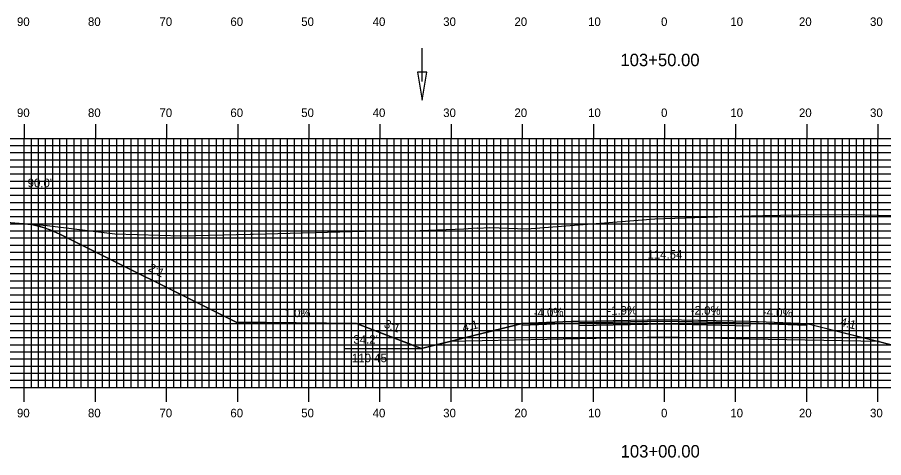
# Model space of a CAD drawing. Extents: x 1767300 to 1767643, y 442591 to 442811.
# Drawn here: x 1767375 to 1767496.7, y 442653.8 to 442715.7 of the extents above; entities that cross this region are included whole.
import ezdxf

# ---------------------------------------------------------------- set-up
doc = ezdxf.new("R2010")
doc.units = 0
for name, color, linetype in [('ANNOTATION', 7, 'Continuous'), ('D_Drainage_Ditch_Line', 7, 'Continuous'), ('D_Roadway_Centerline', 7, 'Continuous'), ('D_Roadway_Centerline_Text', 7, 'Continuous'), ('D_Roadway_Edge_Shoulder', 7, 'Continuous'), ('D_Roadway_Edge_TW', 7, 'Continuous'), ('D_Roadway_Pavement', 7, 'Continuous'), ('D_Roadway_SlopeLines', 7, 'Continuous'), ('D_Roadway_SubGrade', 7, 'Continuous'), ('D_Text_Standard', 7, 'Continuous'), ('H_V ANNOTATION', 7, 'Continuous'), ('MAJOR', 7, 'Continuous'), ('MINOR', 7, 'Continuous'), ('PDRAIN', 7, 'Continuous'), ('S_Roadway_Centerline', 7, 'Continuous')]:
    doc.layers.add(name, color=color, linetype=linetype)

msp = doc.modelspace()

# ---------------------------------------------------------------- linework, layer by layer
at = {"layer": 'D_Drainage_Ditch_Line'}
msp.add_line((1767431.87, 442706.66), (1767431.87, 442711.36), dxfattribs=at)
msp.add_lwpolyline([(1767432.53, 442707.97), (1767431.22, 442707.97), (1767431.87, 442704.03)], close=True, dxfattribs=at)
at = {"layer": 'D_Roadway_Centerline'}
msp.add_lwpolyline([(1767375.94, 442686.68), (1767376.9, 442686.55), (1767377.19, 442686.51), (1767377.74, 442686.38), (1767378.44, 442686.21), (1767378.79, 442686.09), (1767379.69, 442685.78), (1767380.94, 442685.22), (1767405.72, 442672.83), (1767405.72, 442672.83), (1767410.78, 442672.78), (1767422.65, 442672.66), (1767422.65, 442672.66), (1767430.73, 442669.52), (1767431.76, 442669.12), (1767432.36, 442669.27), (1767435.76, 442670.12), (1767445.94, 442672.66), (1767453.94, 442672.98), (1767465.94, 442673.21), (1767477.93, 442672.97), (1767477.94, 442672.97), (1767482.58, 442672.78), (1767485.94, 442672.65), (1767491.01, 442671.38), (1767496.11, 442670.1), (1767496.11, 442670.1), (1767500.11, 442669.1)], dxfattribs=at)
at = {"layer": 'D_Roadway_Edge_Shoulder'}
for points in [[(1767453.94, 442672.98), (1767445.94, 442672.66), (1767445.94, 442672.41), (1767453.94, 442672.73)], [(1767477.94, 442672.97), (1767485.94, 442672.65), (1767485.94, 442672.4), (1767477.94, 442672.72)]]:
    msp.add_lwpolyline(points, close=True, dxfattribs=at)
at = {"layer": 'D_Roadway_Edge_TW'}
msp.add_lwpolyline([(1767453.94, 442672.73), (1767453.94, 442672.98), (1767465.94, 442673.21), (1767477.94, 442672.97), (1767477.94, 442672.72), (1767465.94, 442672.96)], close=True, dxfattribs=at)
at = {"layer": 'D_Roadway_Pavement'}
msp.add_lwpolyline([(1767453.94, 442672.32), (1767453.94, 442672.73), (1767465.94, 442672.96), (1767477.94, 442672.72), (1767477.94, 442672.3), (1767465.94, 442672.54)], close=True, dxfattribs=at)
at = {"layer": 'D_Roadway_SlopeLines'}
for points in [[(1767422.65, 442672.66), (1767405.72, 442672.83), (1767380.94, 442685.22), (1767379.69, 442685.78), (1767378.44, 442686.21), (1767377.19, 442686.51), (1767375.94, 442686.68)], [(1767431.76, 442669.12), (1767422.65, 442672.66)], [(1767445.94, 442672.66), (1767431.76, 442669.12)], [(1767485.94, 442672.65), (1767500.11, 442669.1)]]:
    msp.add_lwpolyline(points, dxfattribs=at)
at = {"layer": 'D_Roadway_SubGrade'}
msp.add_lwpolyline([(1767453.94, 442670.48), (1767435.76, 442670.12), (1767445.94, 442672.66), (1767445.94, 442672.41), (1767453.94, 442672.73), (1767465.94, 442672.96), (1767477.94, 442672.72), (1767485.94, 442672.4), (1767485.94, 442672.65), (1767496.11, 442670.1), (1767477.94, 442670.47), (1767465.94, 442670.71)], close=True, dxfattribs=at)
at = {"layer": 'MAJOR'}
for p, q in [((1767375.94, 442700.67), (1767375.94, 442698.67)), ((1767385.94, 442700.67), (1767385.94, 442698.67)), ((1767395.94, 442700.67), (1767395.94, 442698.67)), ((1767405.94, 442700.67), (1767405.94, 442698.67)), ((1767415.94, 442700.67), (1767415.94, 442698.67)), ((1767425.94, 442700.67), (1767425.94, 442698.67)), ((1767435.94, 442700.67), (1767435.94, 442698.67)), ((1767445.94, 442700.67), (1767445.94, 442698.67)), ((1767455.94, 442700.67), (1767455.94, 442698.67)), ((1767465.94, 442700.67), (1767465.94, 442698.67)), ((1767475.94, 442700.67), (1767475.94, 442698.67)), ((1767485.94, 442700.67), (1767485.94, 442698.67)), ((1767495.94, 442700.67), (1767495.94, 442698.67)), ((1767325.94, 442698.67), (1767605.94, 442698.67)), ((1767325.94, 442698.67), (1767605.94, 442698.67)), ((1767375.94, 442663.67), (1767375.94, 442698.67)), ((1767385.94, 442663.67), (1767385.94, 442698.67)), ((1767395.94, 442663.67), (1767395.94, 442698.67)), ((1767405.94, 442663.67), (1767405.94, 442698.67)), ((1767415.94, 442663.67), (1767415.94, 442698.67)), ((1767425.94, 442663.67), (1767425.94, 442698.67)), ((1767435.94, 442663.67), (1767435.94, 442698.67)), ((1767445.94, 442663.67), (1767445.94, 442698.67)), ((1767455.94, 442663.67), (1767455.94, 442698.67)), ((1767465.94, 442663.67), (1767465.94, 442698.67)), ((1767475.94, 442663.67), (1767475.94, 442698.67)), ((1767485.94, 442663.67), (1767485.94, 442698.67)), ((1767495.94, 442663.67), (1767495.94, 442698.67)), ((1767325.94, 442693.67), (1767605.94, 442693.67)), ((1767325.94, 442688.67), (1767605.94, 442688.67)), ((1767325.94, 442683.67), (1767605.94, 442683.67)), ((1767325.94, 442678.67), (1767605.94, 442678.67)), ((1767325.94, 442673.67), (1767605.94, 442673.67)), ((1767325.94, 442668.67), (1767605.94, 442668.67)), ((1767325.94, 442663.67), (1767605.94, 442663.67)), ((1767325.94, 442663.67), (1767605.94, 442663.67)), ((1767375.94, 442661.66), (1767375.94, 442663.67)), ((1767385.94, 442661.66), (1767385.94, 442663.67)), ((1767395.94, 442661.66), (1767395.94, 442663.67)), ((1767405.94, 442661.66), (1767405.94, 442663.67)), ((1767415.94, 442661.66), (1767415.94, 442663.67)), ((1767425.94, 442661.66), (1767425.94, 442663.67)), ((1767435.94, 442661.66), (1767435.94, 442663.67)), ((1767445.94, 442661.66), (1767445.94, 442663.67)), ((1767455.94, 442661.66), (1767455.94, 442663.67)), ((1767465.94, 442661.66), (1767465.94, 442663.67)), ((1767475.94, 442661.66), (1767475.94, 442663.67)), ((1767485.94, 442661.66), (1767485.94, 442663.67)), ((1767495.94, 442661.66), (1767495.94, 442663.67))]:
    msp.add_line(p, q, dxfattribs=at)
at = {"layer": 'MINOR'}
for p, q in [((1767376.94, 442663.67), (1767376.94, 442698.67)), ((1767377.94, 442663.67), (1767377.94, 442698.67)), ((1767378.94, 442663.67), (1767378.94, 442698.67)), ((1767379.94, 442663.67), (1767379.94, 442698.67)), ((1767380.94, 442663.67), (1767380.94, 442698.67)), ((1767381.94, 442663.67), (1767381.94, 442698.67)), ((1767382.94, 442663.67), (1767382.94, 442698.67)), ((1767383.94, 442663.67), (1767383.94, 442698.67)), ((1767384.94, 442663.67), (1767384.94, 442698.67)), ((1767386.94, 442663.67), (1767386.94, 442698.67)), ((1767387.94, 442663.67), (1767387.94, 442698.67)), ((1767388.94, 442663.67), (1767388.94, 442698.67)), ((1767389.94, 442663.67), (1767389.94, 442698.67)), ((1767390.94, 442663.67), (1767390.94, 442698.67)), ((1767391.94, 442663.67), (1767391.94, 442698.67)), ((1767392.94, 442663.67), (1767392.94, 442698.67)), ((1767393.94, 442663.67), (1767393.94, 442698.67)), ((1767394.94, 442663.67), (1767394.94, 442698.67)), ((1767396.94, 442663.67), (1767396.94, 442698.67)), ((1767397.94, 442663.67), (1767397.94, 442698.67)), ((1767398.94, 442663.67), (1767398.94, 442698.67)), ((1767399.94, 442663.67), (1767399.94, 442698.67)), ((1767400.94, 442663.67), (1767400.94, 442698.67)), ((1767401.94, 442663.67), (1767401.94, 442698.67)), ((1767402.94, 442663.67), (1767402.94, 442698.67)), ((1767403.94, 442663.67), (1767403.94, 442698.67)), ((1767404.94, 442663.67), (1767404.94, 442698.67)), ((1767406.94, 442663.67), (1767406.94, 442698.67)), ((1767407.94, 442663.67), (1767407.94, 442698.67)), ((1767408.94, 442663.67), (1767408.94, 442698.67)), ((1767409.94, 442663.67), (1767409.94, 442698.67)), ((1767410.94, 442663.67), (1767410.94, 442698.67)), ((1767411.94, 442663.67), (1767411.94, 442698.67)), ((1767412.94, 442663.67), (1767412.94, 442698.67)), ((1767413.94, 442663.67), (1767413.94, 442698.67)), ((1767414.94, 442663.67), (1767414.94, 442698.67)), ((1767416.94, 442663.67), (1767416.94, 442698.67)), ((1767417.94, 442663.67), (1767417.94, 442698.67)), ((1767418.94, 442663.67), (1767418.94, 442698.67)), ((1767419.94, 442663.67), (1767419.94, 442698.67)), ((1767420.94, 442663.67), (1767420.94, 442698.67)), ((1767421.94, 442663.67), (1767421.94, 442698.67)), ((1767422.94, 442663.67), (1767422.94, 442698.67)), ((1767423.94, 442663.67), (1767423.94, 442698.67)), ((1767424.94, 442663.67), (1767424.94, 442698.67)), ((1767426.94, 442663.67), (1767426.94, 442698.67)), ((1767427.94, 442663.67), (1767427.94, 442698.67)), ((1767428.94, 442663.67), (1767428.94, 442698.67)), ((1767429.94, 442663.67), (1767429.94, 442698.67)), ((1767430.94, 442663.67), (1767430.94, 442698.67)), ((1767431.94, 442663.67), (1767431.94, 442698.67)), ((1767432.94, 442663.67), (1767432.94, 442698.67)), ((1767433.94, 442663.67), (1767433.94, 442698.67)), ((1767434.94, 442663.67), (1767434.94, 442698.67)), ((1767436.94, 442663.67), (1767436.94, 442698.67)), ((1767437.94, 442663.67), (1767437.94, 442698.67)), ((1767438.94, 442663.67), (1767438.94, 442698.67)), ((1767439.94, 442663.67), (1767439.94, 442698.67)), ((1767440.94, 442663.67), (1767440.94, 442698.67)), ((1767441.94, 442663.67), (1767441.94, 442698.67)), ((1767442.94, 442663.67), (1767442.94, 442698.67)), ((1767443.94, 442663.67), (1767443.94, 442698.67)), ((1767444.94, 442663.67), (1767444.94, 442698.67)), ((1767446.94, 442663.67), (1767446.94, 442698.67)), ((1767447.94, 442663.67), (1767447.94, 442698.67)), ((1767448.94, 442663.67), (1767448.94, 442698.67)), ((1767449.94, 442663.67), (1767449.94, 442698.67)), ((1767450.94, 442663.67), (1767450.94, 442698.67)), ((1767451.94, 442663.67), (1767451.94, 442698.67)), ((1767452.94, 442663.67), (1767452.94, 442698.67)), ((1767453.94, 442663.67), (1767453.94, 442698.67)), ((1767454.94, 442663.67), (1767454.94, 442698.67)), ((1767456.94, 442663.67), (1767456.94, 442698.67)), ((1767457.94, 442663.67), (1767457.94, 442698.67)), ((1767458.94, 442663.67), (1767458.94, 442698.67)), ((1767459.94, 442663.67), (1767459.94, 442698.67)), ((1767460.94, 442663.67), (1767460.94, 442698.67)), ((1767461.94, 442663.67), (1767461.94, 442698.67)), ((1767462.94, 442663.67), (1767462.94, 442698.67)), ((1767463.94, 442663.67), (1767463.94, 442698.67)), ((1767464.94, 442663.67), (1767464.94, 442698.67)), ((1767466.94, 442663.67), (1767466.94, 442698.67)), ((1767467.94, 442663.67), (1767467.94, 442698.67)), ((1767468.94, 442663.67), (1767468.94, 442698.67)), ((1767469.94, 442663.67), (1767469.94, 442698.67)), ((1767470.94, 442663.67), (1767470.94, 442698.67)), ((1767471.94, 442663.67), (1767471.94, 442698.67)), ((1767472.94, 442663.67), (1767472.94, 442698.67)), ((1767473.94, 442663.67), (1767473.94, 442698.67)), ((1767474.94, 442663.67), (1767474.94, 442698.67)), ((1767476.94, 442663.67), (1767476.94, 442698.67)), ((1767477.94, 442663.67), (1767477.94, 442698.67)), ((1767478.94, 442663.67), (1767478.94, 442698.67)), ((1767479.94, 442663.67), (1767479.94, 442698.67)), ((1767480.94, 442663.67), (1767480.94, 442698.67)), ((1767481.94, 442663.67), (1767481.94, 442698.67)), ((1767482.94, 442663.67), (1767482.94, 442698.67)), ((1767483.94, 442663.67), (1767483.94, 442698.67)), ((1767484.94, 442663.67), (1767484.94, 442698.67)), ((1767486.94, 442663.67), (1767486.94, 442698.67)), ((1767487.94, 442663.67), (1767487.94, 442698.67)), ((1767488.94, 442663.67), (1767488.94, 442698.67)), ((1767489.94, 442663.67), (1767489.94, 442698.67)), ((1767490.94, 442663.67), (1767490.94, 442698.67)), ((1767491.94, 442663.67), (1767491.94, 442698.67)), ((1767492.94, 442663.67), (1767492.94, 442698.67)), ((1767493.94, 442663.67), (1767493.94, 442698.67)), ((1767494.94, 442663.67), (1767494.94, 442698.67)), ((1767325.94, 442697.67), (1767605.94, 442697.67)), ((1767325.94, 442696.67), (1767605.94, 442696.67)), ((1767325.94, 442695.67), (1767605.94, 442695.67)), ((1767325.94, 442694.67), (1767605.94, 442694.67)), ((1767325.94, 442692.67), (1767605.94, 442692.67)), ((1767325.94, 442691.67), (1767605.94, 442691.67)), ((1767325.94, 442690.67), (1767605.94, 442690.67)), ((1767325.94, 442689.67), (1767605.94, 442689.67)), ((1767325.94, 442687.67), (1767605.94, 442687.67)), ((1767325.94, 442686.67), (1767605.94, 442686.67)), ((1767325.94, 442685.67), (1767605.94, 442685.67)), ((1767325.94, 442684.67), (1767605.94, 442684.67)), ((1767325.94, 442682.67), (1767605.94, 442682.67)), ((1767325.94, 442681.67), (1767605.94, 442681.67)), ((1767325.94, 442680.67), (1767605.94, 442680.67)), ((1767325.94, 442679.67), (1767605.94, 442679.67)), ((1767325.94, 442677.67), (1767605.94, 442677.67)), ((1767325.94, 442676.67), (1767605.94, 442676.67)), ((1767325.94, 442675.67), (1767605.94, 442675.67)), ((1767325.94, 442674.67), (1767605.94, 442674.67)), ((1767325.94, 442672.67), (1767605.94, 442672.67)), ((1767325.94, 442671.67), (1767605.94, 442671.67)), ((1767325.94, 442670.67), (1767605.94, 442670.67)), ((1767325.94, 442669.67), (1767605.94, 442669.67)), ((1767325.94, 442667.67), (1767605.94, 442667.67)), ((1767325.94, 442666.67), (1767605.94, 442666.67)), ((1767325.94, 442665.67), (1767605.94, 442665.67)), ((1767325.94, 442664.67), (1767605.94, 442664.67))]:
    msp.add_line(p, q, dxfattribs=at)
at = {"layer": 'PDRAIN'}
msp.add_line((1767421.04, 442669.12), (1767431.76, 442669.12), dxfattribs=at)
at = {"layer": 'S_Roadway_Centerline'}
msp.add_lwpolyline([(1767370.06, 442687.16), (1767379.16, 442686.41), (1767388.65, 442685.27), (1767398.09, 442684.97), (1767407.68, 442685.21), (1767407.93, 442685.22), (1767408.1, 442685.23), (1767425.49, 442685.69), (1767427.52, 442685.69), (1767429.05, 442685.62), (1767437.74, 442685.96), (1767439.59, 442686.08), (1767439.65, 442686.06), (1767441.38, 442686.14), (1767446.59, 442685.97), (1767456.34, 442686.7), (1767464.57, 442687.36), (1767470.22, 442687.55), (1767479.78, 442687.82), (1767484.71, 442687.93), (1767492.19, 442687.95), (1767503.68, 442687.68)], dxfattribs=at)

# ---------------------------------------------------------------- texts
at = {"layer": 'ANNOTATION'}
for s, rotation, p in [('2:1', 333.4347, (1767393.26, 442680.1)), ('-1.9%', 1.0646, (1767457.91, 442673.86)), ('-2.0%', 358.8542, (1767469.62, 442673.93)), ('1.0%', 359.4281, (1767412.51, 442673.56)), ('-4.0%', 2.2905, (1767447.57, 442673.53)), ('-4.0%', 357.7093, (1767479.73, 442673.7)), ('3:1', 338.748, (1767426.41, 442672.15)), ('4:1', 14.039, (1767437.68, 442671.46)), ('4:1', 345.9612, (1767490.53, 442672.36))]:
    msp.add_text(s, height=1.2, rotation=rotation, dxfattribs=at).set_placement(p)
for s, p in [("34.2'", (1767422.2, 442669.81)), ('110.45', (1767422, 442667.21))]:
    msp.add_text(s, height=1.2, dxfattribs=at).set_placement(p)
at = {"layer": 'D_Roadway_Centerline'}
for s, p in [('C', (1767465.93, 442673.21)), ('L', (1767465.94, 442673.2))]:
    msp.add_text(s, height=0.0146, dxfattribs=at).set_placement(p)
at = {"layer": 'D_Roadway_Centerline_Text'}
msp.add_text('114.54', height=1.2, dxfattribs=at).set_placement((1767463.54, 442681.76))
at = {"layer": 'D_Text_Standard'}
msp.add_text("90.0'", height=1.2, dxfattribs=at).set_placement((1767376.41, 442691.81))
at = {"layer": 'H_V ANNOTATION'}
for s, height, p in [('90', 1.2, (1767374.91, 442714.47)), ('80', 1.2, (1767384.89, 442714.47)), ('70', 1.2, (1767394.94, 442714.47)), ('60', 1.2, (1767404.91, 442714.47)), ('50', 1.2, (1767414.87, 442714.47)), ('40', 1.2, (1767424.91, 442714.47)), ('30', 1.2, (1767434.83, 442714.47)), ('20', 1.2, (1767444.84, 442714.47)), ('10', 1.2, (1767455.19, 442714.47)), ('0', 1.2, (1767465.45, 442714.47)), ('10', 1.2, (1767475.19, 442714.47)), ('20', 1.2, (1767484.84, 442714.47)), ('30', 1.2, (1767494.83, 442714.47)), ('103+50.00', 1.75, (1767459.74, 442708.82)), ('90', 1.2, (1767374.91, 442701.67)), ('80', 1.2, (1767384.89, 442701.67)), ('70', 1.2, (1767394.94, 442701.67)), ('60', 1.2, (1767404.91, 442701.67)), ('50', 1.2, (1767414.87, 442701.67)), ('40', 1.2, (1767424.91, 442701.67)), ('30', 1.2, (1767434.83, 442701.67)), ('20', 1.2, (1767444.84, 442701.67)), ('10', 1.2, (1767455.19, 442701.67)), ('0', 1.2, (1767465.45, 442701.67)), ('10', 1.2, (1767475.19, 442701.67)), ('20', 1.2, (1767484.84, 442701.67)), ('30', 1.2, (1767494.83, 442701.67)), ('90', 1.2, (1767374.91, 442659.47)), ('80', 1.2, (1767384.89, 442659.47)), ('70', 1.2, (1767394.94, 442659.47)), ('60', 1.2, (1767404.91, 442659.47)), ('50', 1.2, (1767414.87, 442659.47)), ('40', 1.2, (1767424.91, 442659.47)), ('30', 1.2, (1767434.83, 442659.47)), ('20', 1.2, (1767444.84, 442659.47)), ('10', 1.2, (1767455.19, 442659.47)), ('0', 1.2, (1767465.45, 442659.47)), ('10', 1.2, (1767475.19, 442659.47)), ('20', 1.2, (1767484.84, 442659.47)), ('30', 1.2, (1767494.83, 442659.47)), ('103+00.00', 1.75, (1767459.77, 442653.82))]:
    msp.add_text(s, height=height, dxfattribs=at).set_placement(p)

doc.saveas('drawing.dxf')
